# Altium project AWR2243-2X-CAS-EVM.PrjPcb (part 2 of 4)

## Sheet SOC_IO.schdoc
size A2; Date: Not shown in title block; ApprovedBy: Not shown in title block; CheckedBy: Not shown in title block; Author: Not shown in title block; CompanyName: Not shown in title block; DrawnBy: B. Shaffer; Engineer: Not shown in title block; Organization: Not shown in title block; Address1: Not shown in title block; Address2: Not shown in title block; Address3: Not shown in title block; Address4: Not shown in title block; DocumentNumber: 4; Revision: Use project parameter SCH_Rev; SheetNumber: 4; SheetTotal: 17; PageSetup: Record=PageOptions¦CenterHorizontal=True¦CenterVertical=True¦PrintScale=1.00¦XCorrection=1.00¦YCorrection=1.00¦PrintKind=0¦BorderSize=5000000¦LeftOffset=0¦BottomOffset=0¦Orientation=2¦PaperLength=1000¦PaperWidth=1000¦Scale=100¦PaperSource=15¦PrintQuality=600¦MediaType=1¦DitherType=10¦PaperKind=Letter¦PrintScaleMode=1
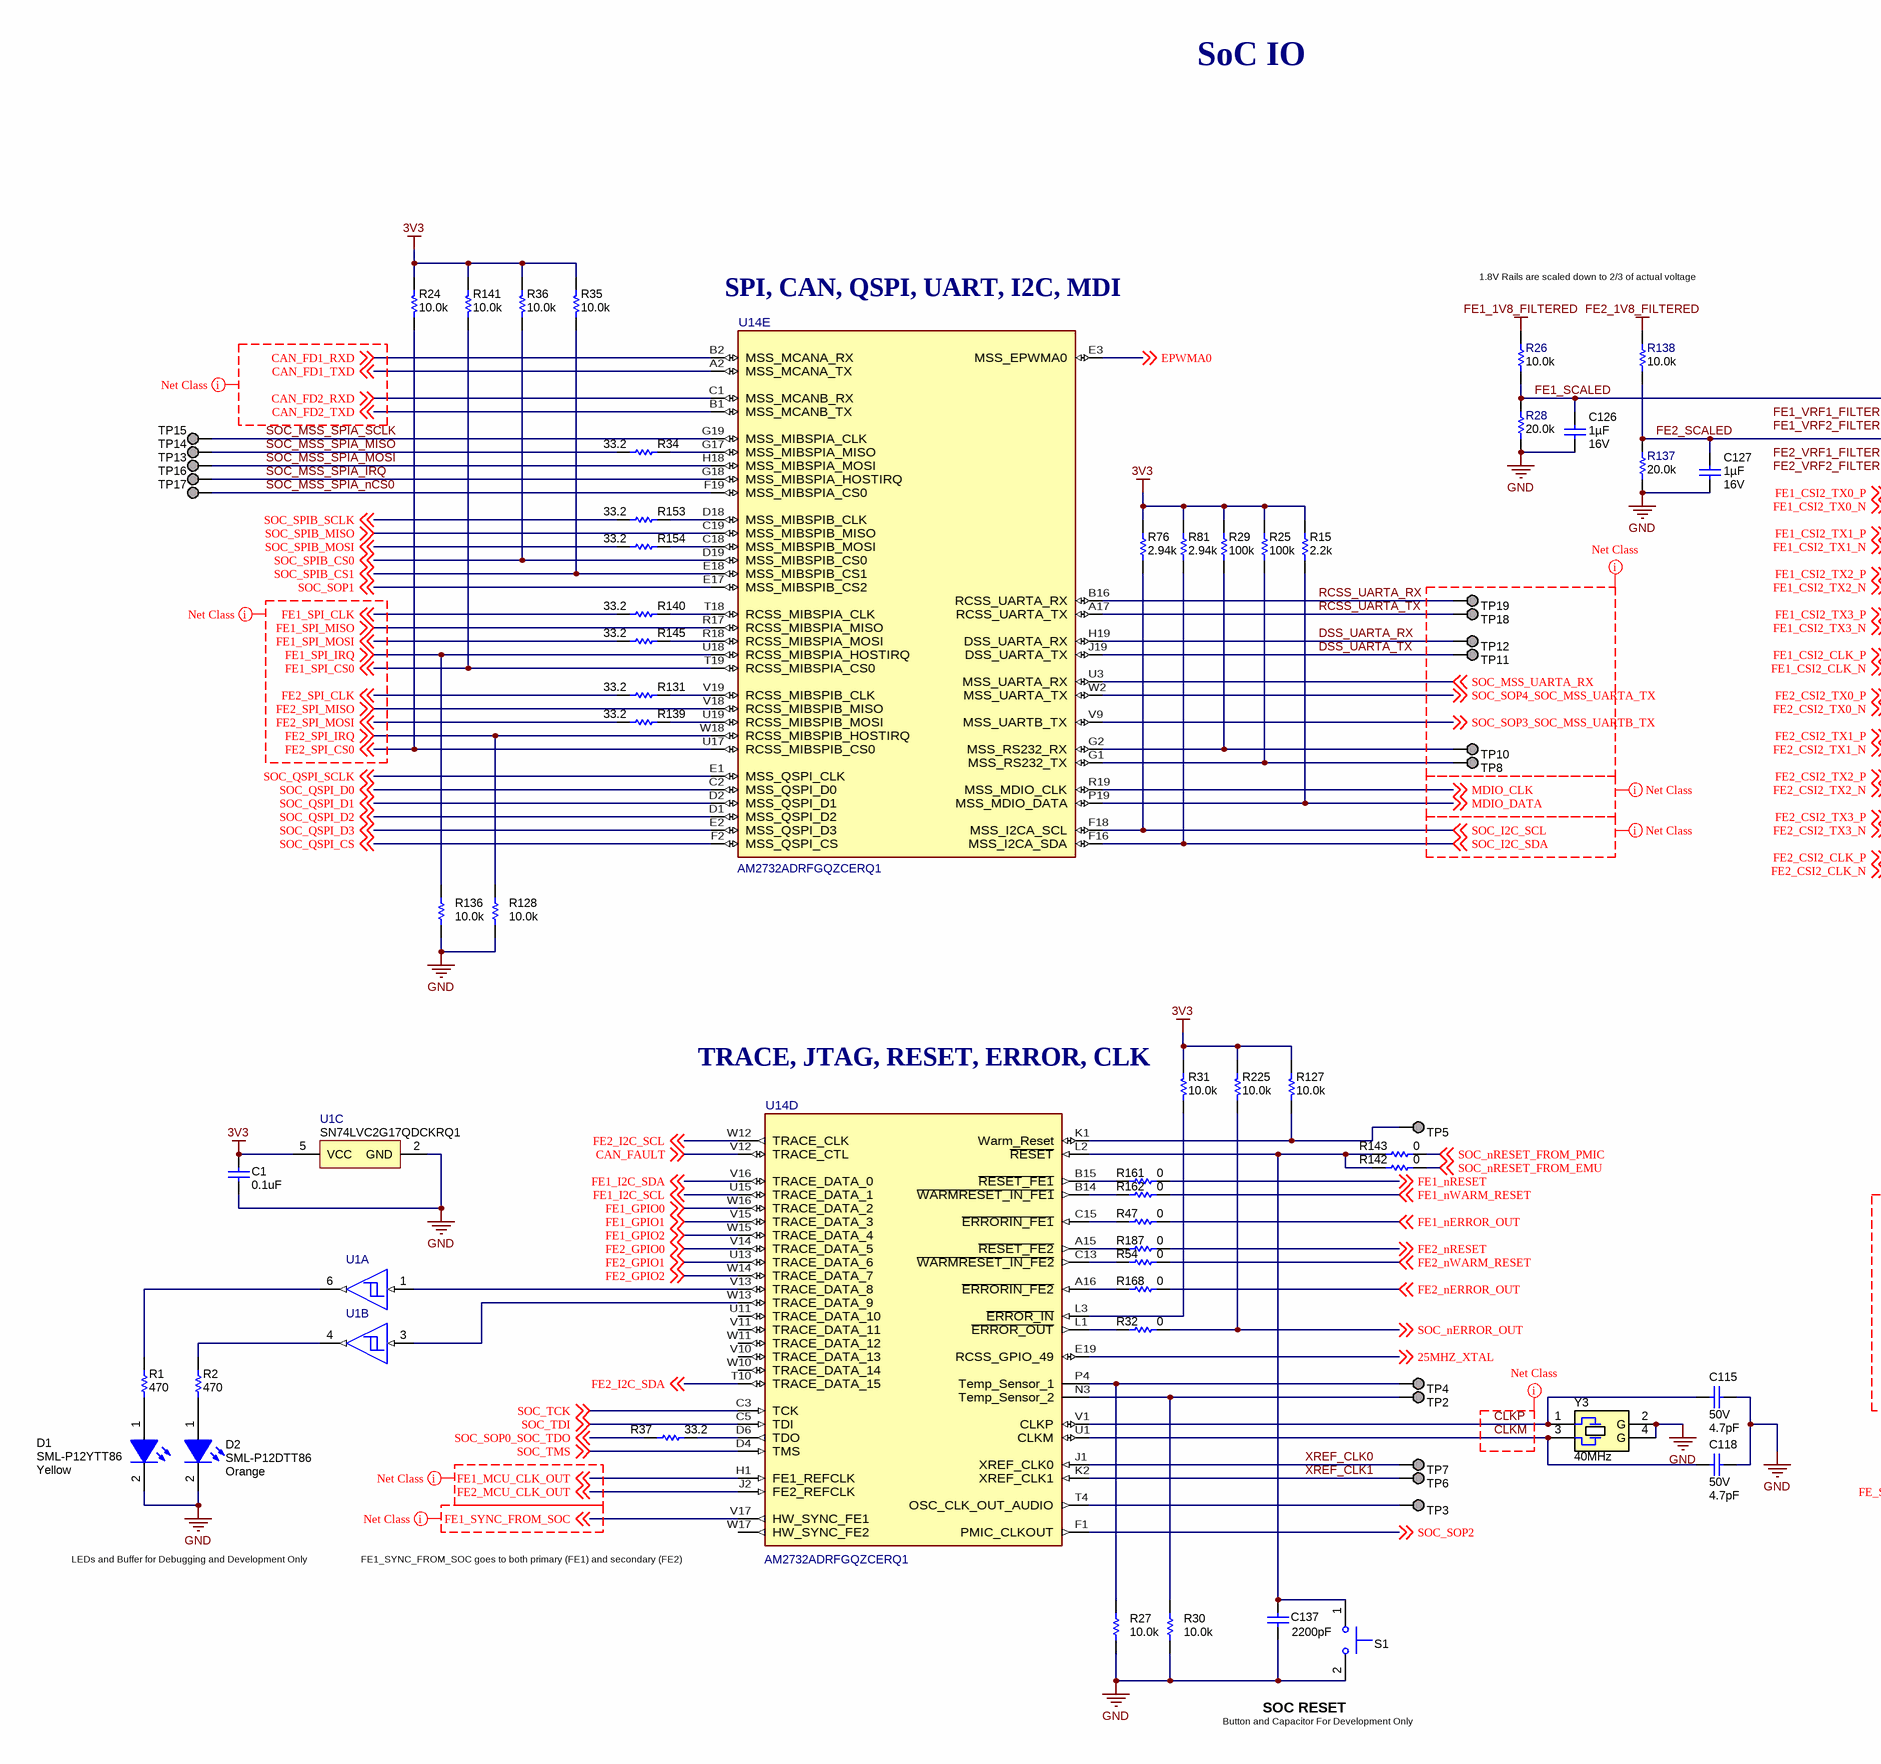
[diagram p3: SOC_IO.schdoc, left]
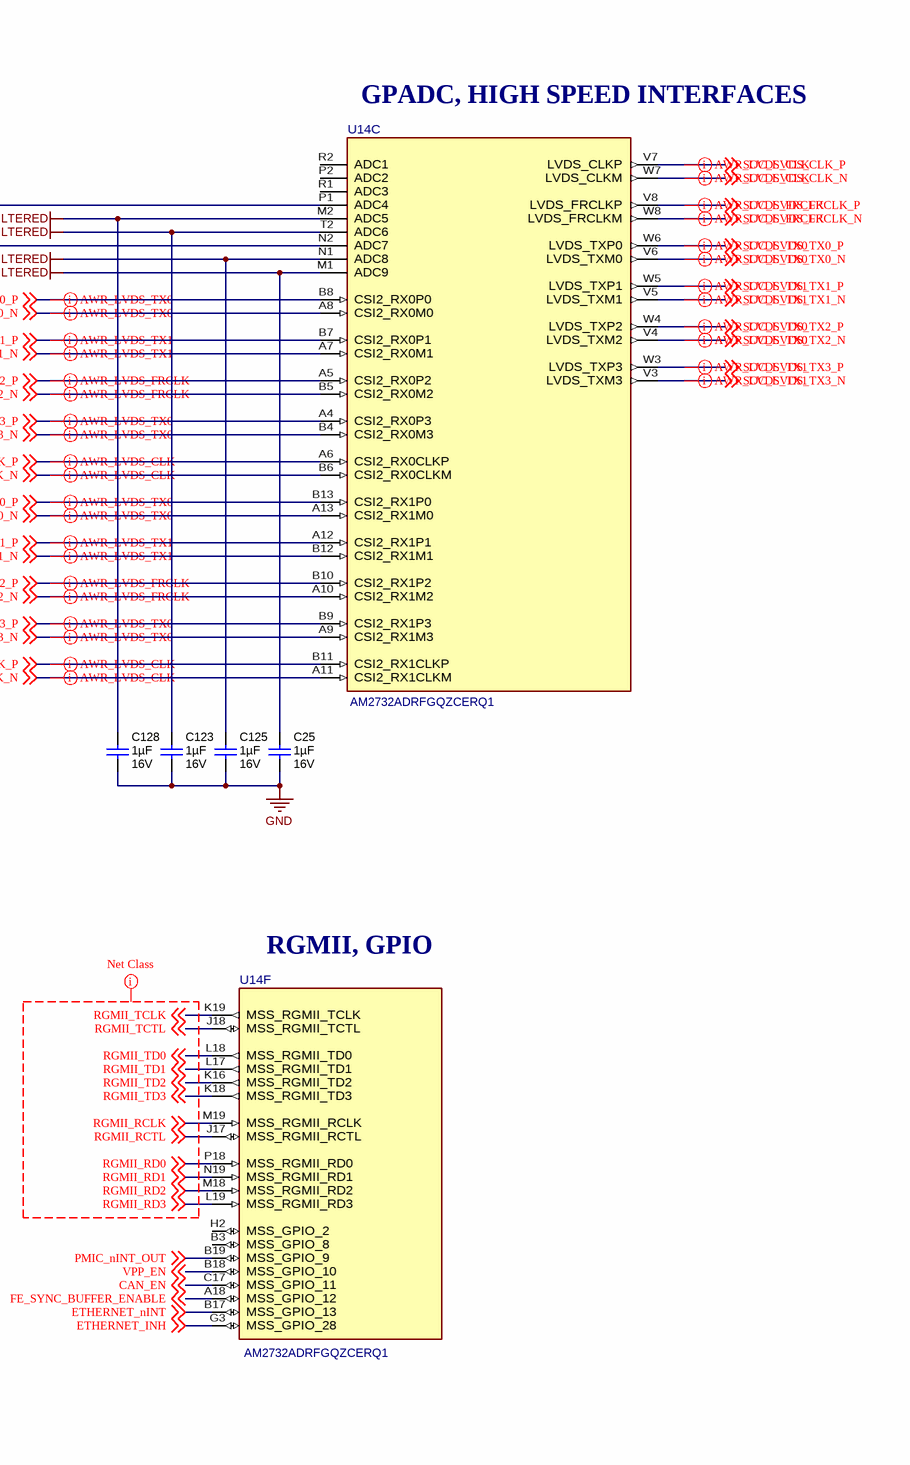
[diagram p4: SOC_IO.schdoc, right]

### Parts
(Parts that share a designator on the sheet are numbered #1, #2 ... from top to bottom, then left to right.)
C1  ValueDisplayed: 0.1uF  [0402L]  (hidden comment: GCM155R71C104KA55D)
C25  VDC_V: 16V  ValueDisplayed: 1µF  [0603S]  (hidden comment: GCM188R71C105KA64J)
C115  VDC_V: 50V  ValueDisplayed: 4.7pF  [0402]  (hidden comment: GJM1555C1H4R7BB01D)
C118  VDC_V: 50V  ValueDisplayed: 4.7pF  [0402]  (hidden comment: GJM1555C1H4R7BB01D)
C123  VDC_V: 16V  ValueDisplayed: 1µF  [0603S]  (hidden comment: GCM188R71C105KA64J)
C125  VDC_V: 16V  ValueDisplayed: 1µF  [0603S]  (hidden comment: GCM188R71C105KA64J)
C126  VDC_V: 16V  ValueDisplayed: 1µF  [0603S]  (hidden comment: GCM188R71C105KA64J)
C127  VDC_V: 16V  ValueDisplayed: 1µF  [0603S]  (hidden comment: GCM188R71C105KA64J)
C128  VDC_V: 16V  ValueDisplayed: 1µF  [0603S]  (hidden comment: GCM188R71C105KA64J)
C137  value 2200pF  [0402]  (hidden comment: UMK105B7222KV-F)
D1  SML-P12YTT86  value Yellow  [LED_SMLP12_YELLOW]
D2  SML-P12DTT86  value Orange  [LED_SMLP12_ORANGE]
R1  ValueDisplayed: 470  [0402]  (hidden comment: ERJ-2RKF4700X)
R2  ValueDisplayed: 470  [0402]  (hidden comment: ERJ-2RKF4700X)
R15  ValueDisplayed: 2.2k  [0402]  (hidden comment: CRCW04022K20JNED)
R24  ValueDisplayed: 10.0k  [0402]  (hidden comment: CRCW040210K0FKED)
R25  ValueDisplayed: 100k  [0402]  (hidden comment: CRCW0402100KFKED)
R26  ValueDisplayed: 10.0k  [0402]  (hidden comment: CRCW040210K0DHEDP)
R27  ValueDisplayed: 10.0k  [0402]  (hidden comment: CRCW040210K0FKED)
R28  ValueDisplayed: 20.0k  [0402]  (hidden comment: CRCW040220K0FKED)
R29  ValueDisplayed: 100k  [0402]  (hidden comment: CRCW0402100KFKED)
R30  ValueDisplayed: 10.0k  [0402]  (hidden comment: CRCW040210K0FKED)
R31  ValueDisplayed: 10.0k  [0402]  (hidden comment: CRCW040210K0FKED)
R32  ValueDisplayed: 0  [0201]  (hidden comment: CRCW02010000Z0ED)
R34  ValueDisplayed: 33.2  [0402]  (hidden comment: CRCW040233R2FKED)
R35  ValueDisplayed: 10.0k  [0402]  (hidden comment: CRCW040210K0FKED)
R36  ValueDisplayed: 10.0k  [0402]  (hidden comment: CRCW040210K0FKED)
R37  ValueDisplayed: 33.2  [0402]  (hidden comment: CRCW040233R2FKED)
R47  ValueDisplayed: 0  [0201]  (hidden comment: CRCW02010000Z0ED)
R54  ValueDisplayed: 0  [0201]  (hidden comment: CRCW02010000Z0ED)
R76  ValueDisplayed: 2.94k  [0402]  (hidden comment: CRCW04022K94FKED)
R81  ValueDisplayed: 2.94k  [0402]  (hidden comment: CRCW04022K94FKED)
R127  ValueDisplayed: 10.0k  [0402]  (hidden comment: CRCW040210K0FKED)
R128  ValueDisplayed: 10.0k  [0402]  (hidden comment: CRCW040210K0FKED)
R131  ValueDisplayed: 33.2  [0402]  (hidden comment: CRCW040233R2FKED)
R136  ValueDisplayed: 10.0k  [0402]  (hidden comment: CRCW040210K0FKED)
R137  ValueDisplayed: 20.0k  [0402]  (hidden comment: CRCW040220K0FKED)
R138  ValueDisplayed: 10.0k  [0402]  (hidden comment: CRCW040210K0DHEDP)
R139  ValueDisplayed: 33.2  [0402]  (hidden comment: CRCW040233R2FKED)
R140  ValueDisplayed: 33.2  [0402]  (hidden comment: CRCW040233R2FKED)
R141  ValueDisplayed: 10.0k  [0402]  (hidden comment: CRCW040210K0FKED)
R142  ValueDisplayed: 0  [0402]  (hidden comment: CRCW04020000Z0ED)
R143  ValueDisplayed: 0  [0402]  (hidden comment: CRCW04020000Z0ED)
R145  ValueDisplayed: 33.2  [0402]  (hidden comment: CRCW040233R2FKED)
R153  ValueDisplayed: 33.2  [0402]  (hidden comment: CRCW040233R2FKED)
R154  ValueDisplayed: 33.2  [0402]  (hidden comment: CRCW040233R2FKED)
R161  ValueDisplayed: 0  [0201]  (hidden comment: CRCW02010000Z0ED)
R162  ValueDisplayed: 0  [0201]  (hidden comment: CRCW02010000Z0ED)
R168  ValueDisplayed: 0  [0201]  (hidden comment: CRCW02010000Z0ED)
R187  ValueDisplayed: 0  [0201]  (hidden comment: CRCW02010000Z0ED)
R225  ValueDisplayed: 10.0k  [0402]  (hidden comment: CRCW040210K0FKED)
S1  SKRKAEE010  [SW_SKRKAEE010]  (value not drawn)
TP2  TP_H0.45P0.75  [TP_H045P075]  (value not drawn)  (no BOM)
TP3  TP_H0.45P0.75  [TP_H045P075]  (value not drawn)  (no BOM)
TP4  TP_H0.45P0.75  [TP_H045P075]  (value not drawn)  (no BOM)
TP5  TP_H0.45P0.75  [TP_H045P075]  (value not drawn)  (no BOM)
TP6  TP_H0.45P0.75  [TP_H045P075]  (value not drawn)  (no BOM)
TP7  TP_H0.45P0.75  [TP_H045P075]  (value not drawn)  (no BOM)
TP8  TP_H0.45P0.75  [TP_H045P075]  (value not drawn)  (no BOM)
TP10  TP_H0.45P0.75  [TP_H045P075]  (value not drawn)  (no BOM)
TP11  TP_H0.45P0.75  [TP_H045P075]  (value not drawn)  (no BOM)
TP12  TP_H0.45P0.75  [TP_H045P075]  (value not drawn)  (no BOM)
TP13  TP_H0.45P0.75  [TP_H045P075]  (value not drawn)  (no BOM)
TP14  TP_H0.45P0.75  [TP_H045P075]  (value not drawn)  (no BOM)
TP15  TP_H0.45P0.75  [TP_H045P075]  (value not drawn)  (no BOM)
TP16  TP_H0.45P0.75  [TP_H045P075]  (value not drawn)  (no BOM)
TP17  TP_H0.45P0.75  [TP_H045P075]  (value not drawn)  (no BOM)
TP18  TP_H0.45P0.75  [TP_H045P075]  (value not drawn)  (no BOM)
TP19  TP_H0.45P0.75  [TP_H045P075]  (value not drawn)  (no BOM)
U1#1  SN74LVC2G17QDCKRQ1  [DCK0006A_N]  (part C of 3)
U1#2  SN74LVC2G17QDCKRQ1  [DCK0006A_N]  (value not drawn)  (parts A,B of 3)
U14#2  AM2732ADRFGQZCERQ1  [ZCE0285A-MFG]  (parts C,D,E,F of 7)
Y3  Frequency_Fixed: 40MHz  [Kyocera_CX3225SA]  (hidden comment: CX3225SA40000D0PTWCC)

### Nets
3V3: C1.2 R15.2 R24.2 R25.2 R29.2 R31.2 R35.2 R36.2 R76.2 R81.2 R127.2 R141.2 R225.2 U1#1.5(VCC)
FE1_1V8_FILTERED: R26.2
FE1_VRF1_FILTERED: C128.1 U14#2.M2(ADC5)
FE1_VRF2_FILTERED: C123.1 U14#2.T2(ADC6)
FE2_1V8_FILTERED: R138.2
FE2_VRF1_FILTERED: C125.1 U14#2.N1(ADC8)
FE2_VRF2_FILTERED: C25.1 U14#2.M1(ADC9)
GND: C1.1 C25.2 C115.2 C118.2 C123.2 C125.2 C126.2 C127.2 C128.2 C137.2 D1.2(K) D2.2(K) R27.1 R28.1 R30.1 R128.1 R136.1 R137.1 S1.2 U1#1.2(GND) Y3.2(GND) Y3.4(GND)
25MHZ_XTAL: U14#2.E19(RCSS_GPIO_49) ; off-sheet 25MHZ_XTAL
CAN_EN: U14#2.C17(MSS_GPIO_11) ; off-sheet CAN_EN
CAN_FAULT: U14#2.V12(TRACE_CTL) ; off-sheet CAN_FAULT
CAN_FD1_RXD: U14#2.B2(MSS_MCANA_RX) ; off-sheet CAN_FD1_RXD
CAN_FD1_TXD: U14#2.A2(MSS_MCANA_TX) ; off-sheet CAN_FD1_TXD
CAN_FD2_RXD: U14#2.C1(MSS_MCANB_RX) ; off-sheet CAN_FD2_RXD
CAN_FD2_TXD: U14#2.B1(MSS_MCANB_TX) ; off-sheet CAN_FD2_TXD
CLKM: C118.1 U14#2.U1(CLKM) Y3.3
CLKP: C115.1 U14#2.V1(CLKP) Y3.1
DSS_UARTA_RX: TP12.1 U14#2.H19(DSS_UARTA_RX)
DSS_UARTA_TX: TP11.1 U14#2.J19(DSS_UARTA_TX)
EPWMA0: U14#2.E3(MSS_EPWMA0) ; off-sheet EPWMA0
ETHERNET_INH: U14#2.G3(MSS_GPIO_28) ; off-sheet ETHERNET_INH
ETHERNET_nINT: U14#2.B17(MSS_GPIO_13) ; off-sheet ETHERNET_nINT
FE1_CSI2_CLK_N: U14#2.B6(CSI2_RX0CLKM) ; off-sheet FE1_CSI2_CLK_N
FE1_CSI2_CLK_P: U14#2.A6(CSI2_RX0CLKP) ; off-sheet FE1_CSI2_CLK_P
FE1_CSI2_TX0_N: U14#2.A8(CSI2_RX0M0) ; off-sheet FE1_CSI2_TX0_N
FE1_CSI2_TX0_P: U14#2.B8(CSI2_RX0P0) ; off-sheet FE1_CSI2_TX0_P
FE1_CSI2_TX1_N: U14#2.A7(CSI2_RX0M1) ; off-sheet FE1_CSI2_TX1_N
FE1_CSI2_TX1_P: U14#2.B7(CSI2_RX0P1) ; off-sheet FE1_CSI2_TX1_P
FE1_CSI2_TX2_N: U14#2.B5(CSI2_RX0M2) ; off-sheet FE1_CSI2_TX2_N
FE1_CSI2_TX2_P: U14#2.A5(CSI2_RX0P2) ; off-sheet FE1_CSI2_TX2_P
FE1_CSI2_TX3_N: U14#2.B4(CSI2_RX0M3) ; off-sheet FE1_CSI2_TX3_N
FE1_CSI2_TX3_P: U14#2.A4(CSI2_RX0P3) ; off-sheet FE1_CSI2_TX3_P
FE1_GPIO0: U14#2.W16(TRACE_DATA_2) ; off-sheet FE1_GPIO0
FE1_GPIO1: U14#2.V15(TRACE_DATA_3) ; off-sheet FE1_GPIO1
FE1_GPIO2: U14#2.W15(TRACE_DATA_4) ; off-sheet FE1_GPIO2
FE1_I2C_SCL: U14#2.U15(TRACE_DATA_1) ; off-sheet FE1_I2C_SCL
FE1_I2C_SDA: U14#2.V16(TRACE_DATA_0) ; off-sheet FE1_I2C_SDA
FE1_MCU_CLK_OUT: U14#2.H1(FE1_REFCLK) ; off-sheet FE1_MCU_CLK_OUT
FE1_nERROR_OUT: R47.2 ; off-sheet FE1_nERROR_OUT
FE1_nRESET: R161.2 ; off-sheet FE1_nRESET
FE1_nWARM_RESET: R162.2 ; off-sheet FE1_nWARM_RESET
FE1_SCALED: C126.1 R26.1 R28.2 U14#2.P1(ADC4)
FE1_SPI_CLK: R140.1 ; off-sheet FE1_SPI_CLK
FE1_SPI_CS0: R141.1 U14#2.T19(RCSS_MIBSPIA_CS0) ; off-sheet FE1_SPI_CS0
FE1_SPI_IRQ: R136.2 U14#2.U18(RCSS_MIBSPIA_HOSTIRQ) ; off-sheet FE1_SPI_IRQ
FE1_SPI_MISO: U14#2.R17(RCSS_MIBSPIA_MISO) ; off-sheet FE1_SPI_MISO
FE1_SPI_MOSI: R145.1 ; off-sheet FE1_SPI_MOSI
FE1_SYNC_FROM_SOC: U14#2.V17(HW_SYNC_FE1) ; off-sheet FE1_SYNC_FROM_SOC
FE2_CSI2_CLK_N: U14#2.A11(CSI2_RX1CLKM) ; off-sheet FE2_CSI2_CLK_N
FE2_CSI2_CLK_P: U14#2.B11(CSI2_RX1CLKP) ; off-sheet FE2_CSI2_CLK_P
FE2_CSI2_TX0_N: U14#2.A13(CSI2_RX1M0) ; off-sheet FE2_CSI2_TX0_N
FE2_CSI2_TX0_P: U14#2.B13(CSI2_RX1P0) ; off-sheet FE2_CSI2_TX0_P
FE2_CSI2_TX1_N: U14#2.B12(CSI2_RX1M1) ; off-sheet FE2_CSI2_TX1_N
FE2_CSI2_TX1_P: U14#2.A12(CSI2_RX1P1) ; off-sheet FE2_CSI2_TX1_P
FE2_CSI2_TX2_N: U14#2.A10(CSI2_RX1M2) ; off-sheet FE2_CSI2_TX2_N
FE2_CSI2_TX2_P: U14#2.B10(CSI2_RX1P2) ; off-sheet FE2_CSI2_TX2_P
FE2_CSI2_TX3_N: U14#2.A9(CSI2_RX1M3) ; off-sheet FE2_CSI2_TX3_N
FE2_CSI2_TX3_P: U14#2.B9(CSI2_RX1P3) ; off-sheet FE2_CSI2_TX3_P
FE2_GPIO0: U14#2.V14(TRACE_DATA_5) ; off-sheet FE2_GPIO0
FE2_GPIO1: U14#2.U13(TRACE_DATA_6) ; off-sheet FE2_GPIO1
FE2_GPIO2: U14#2.W14(TRACE_DATA_7) ; off-sheet FE2_GPIO2
FE2_I2C_SCL: U14#2.W12(TRACE_CLK) ; off-sheet FE2_I2C_SCL
FE2_I2C_SDA: U14#2.T10(TRACE_DATA_15) ; off-sheet FE2_I2C_SDA
FE2_MCU_CLK_OUT: U14#2.J2(FE2_REFCLK) ; off-sheet FE2_MCU_CLK_OUT
FE2_nERROR_OUT: R168.2 ; off-sheet FE2_nERROR_OUT
FE2_nRESET: R187.2 ; off-sheet FE2_nRESET
FE2_nWARM_RESET: R54.2 ; off-sheet FE2_nWARM_RESET
FE2_SCALED: C127.1 R137.2 R138.1 U14#2.N2(ADC7)
FE2_SPI_CLK: R131.1 ; off-sheet FE2_SPI_CLK
FE2_SPI_CS0: R24.1 U14#2.U17(RCSS_MIBSPIB_CS0) ; off-sheet FE2_SPI_CS0
FE2_SPI_IRQ: R128.2 U14#2.W18(RCSS_MIBSPIB_HOSTIRQ) ; off-sheet FE2_SPI_IRQ
FE2_SPI_MISO: U14#2.V18(RCSS_MIBSPIB_MISO) ; off-sheet FE2_SPI_MISO
FE2_SPI_MOSI: R139.1 ; off-sheet FE2_SPI_MOSI
FE_SYNC_BUFFER_ENABLE: U14#2.A18(MSS_GPIO_12) ; off-sheet FE_SYNC_BUFFER_ENABLE
MDIO_CLK: U14#2.R19(MSS_MDIO_CLK) ; off-sheet MDIO_CLK
MDIO_DATA: R15.1 U14#2.P19(MSS_MDIO_DATA) ; off-sheet MDIO_DATA
PMIC_nINT_OUT: U14#2.B19(MSS_GPIO_9) ; off-sheet PMIC_nINT_OUT
RCSS_UARTA_RX: TP19.1 U14#2.B16(RCSS_UARTA_RX)
RCSS_UARTA_TX: TP18.1 U14#2.A17(RCSS_UARTA_TX)
RGMII_RCLK: U14#2.M19(MSS_RGMII_RCLK) ; off-sheet RGMII_RCLK
RGMII_RCTL: U14#2.J17(MSS_RGMII_RCTL) ; off-sheet RGMII_RCTL
RGMII_RD0: U14#2.P18(MSS_RGMII_RD0) ; off-sheet RGMII_RD0
RGMII_RD1: U14#2.N19(MSS_RGMII_RD1) ; off-sheet RGMII_RD1
RGMII_RD2: U14#2.M18(MSS_RGMII_RD2) ; off-sheet RGMII_RD2
RGMII_RD3: U14#2.L19(MSS_RGMII_RD3) ; off-sheet RGMII_RD3
RGMII_TCLK: U14#2.K19(MSS_RGMII_TCLK) ; off-sheet RGMII_TCLK
RGMII_TCTL: U14#2.J18(MSS_RGMII_TCTL) ; off-sheet RGMII_TCTL
RGMII_TD0: U14#2.L18(MSS_RGMII_TD0) ; off-sheet RGMII_TD0
RGMII_TD1: U14#2.L17(MSS_RGMII_TD1) ; off-sheet RGMII_TD1
RGMII_TD2: U14#2.K16(MSS_RGMII_TD2) ; off-sheet RGMII_TD2
RGMII_TD3: U14#2.K18(MSS_RGMII_TD3) ; off-sheet RGMII_TD3
SOC_I2C_SCL: R76.1 U14#2.F18(MSS_I2CA_SCL) ; off-sheet SOC_I2C_SCL
SOC_I2C_SDA: R81.1 U14#2.F16(MSS_I2CA_SDA) ; off-sheet SOC_I2C_SDA
SOC_LVDS_CLK_N: U14#2.W7(LVDS_CLKM) ; off-sheet SOC_LVDS_CLK_N
SOC_LVDS_CLK_P: U14#2.V7(LVDS_CLKP) ; off-sheet SOC_LVDS_CLK_P
SOC_LVDS_FRCLK_N: U14#2.W8(LVDS_FRCLKM) ; off-sheet SOC_LVDS_FRCLK_N
SOC_LVDS_FRCLK_P: U14#2.V8(LVDS_FRCLKP) ; off-sheet SOC_LVDS_FRCLK_P
SOC_LVDS_TX0_N: U14#2.V6(LVDS_TXM0) ; off-sheet SOC_LVDS_TX0_N
SOC_LVDS_TX0_P: U14#2.W6(LVDS_TXP0) ; off-sheet SOC_LVDS_TX0_P
SOC_LVDS_TX1_N: U14#2.V5(LVDS_TXM1) ; off-sheet SOC_LVDS_TX1_N
SOC_LVDS_TX1_P: U14#2.W5(LVDS_TXP1) ; off-sheet SOC_LVDS_TX1_P
SOC_LVDS_TX2_N: U14#2.V4(LVDS_TXM2) ; off-sheet SOC_LVDS_TX2_N
SOC_LVDS_TX2_P: U14#2.W4(LVDS_TXP2) ; off-sheet SOC_LVDS_TX2_P
SOC_LVDS_TX3_N: U14#2.V3(LVDS_TXM3) ; off-sheet SOC_LVDS_TX3_N
SOC_LVDS_TX3_P: U14#2.W3(LVDS_TXP3) ; off-sheet SOC_LVDS_TX3_P
SOC_MSS_SPIA_IRQ: TP16.1 U14#2.G18(MSS_MIBSPIA_HOSTIRQ)
SOC_MSS_SPIA_MISO: R34.1 TP14.1
SOC_MSS_SPIA_MOSI: TP13.1 U14#2.H18(MSS_MIBSPIA_MOSI)
SOC_MSS_SPIA_nCS0: TP17.1 U14#2.F19(MSS_MIBSPIA_CS0)
SOC_MSS_SPIA_SCLK: TP15.1 U14#2.G19(MSS_MIBSPIA_CLK)
SOC_MSS_UARTA_RX: U14#2.U3(MSS_UARTA_RX) ; off-sheet SOC_MSS_UARTA_RX
SOC_nERROR_OUT: R32.2 R225.1 ; off-sheet SOC_nERROR_OUT
SOC_nRESET_FROM_EMU: R142.1 ; off-sheet SOC_nRESET_FROM_EMU
SOC_nRESET_FROM_PMIC: R143.1 ; off-sheet SOC_nRESET_FROM_PMIC
SOC_QSPI_CS: U14#2.F2(MSS_QSPI_CS) ; off-sheet SOC_QSPI_CS
SOC_QSPI_D0: U14#2.C2(MSS_QSPI_D0) ; off-sheet SOC_QSPI_D0
SOC_QSPI_D1: U14#2.D2(MSS_QSPI_D1) ; off-sheet SOC_QSPI_D1
SOC_QSPI_D2: U14#2.D1(MSS_QSPI_D2) ; off-sheet SOC_QSPI_D2
SOC_QSPI_D3: U14#2.E2(MSS_QSPI_D3) ; off-sheet SOC_QSPI_D3
SOC_QSPI_SCLK: U14#2.E1(MSS_QSPI_CLK) ; off-sheet SOC_QSPI_SCLK
SOC_SOP0_SOC_TDO: R37.1 ; off-sheet SOC_SOP0_SOC_TDO
SOC_SOP1: U14#2.E17(MSS_MIBSPIB_CS2) ; off-sheet SOC_SOP1
SOC_SOP2: U14#2.F1(PMIC_CLKOUT) ; off-sheet SOC_SOP2
SOC_SOP3_SOC_MSS_UARTB_TX: U14#2.V9(MSS_UARTB_TX) ; off-sheet SOC_SOP3_SOC_MSS_UARTB_TX
SOC_SOP4_SOC_MSS_UARTA_TX: U14#2.W2(MSS_UARTA_TX) ; off-sheet SOC_SOP4_SOC_MSS_UARTA_TX
SOC_SPIB_CS0: R36.1 U14#2.D19(MSS_MIBSPIB_CS0) ; off-sheet SOC_SPIB_CS0
SOC_SPIB_CS1: R35.1 U14#2.E18(MSS_MIBSPIB_CS1) ; off-sheet SOC_SPIB_CS1
SOC_SPIB_MISO: U14#2.C19(MSS_MIBSPIB_MISO) ; off-sheet SOC_SPIB_MISO
SOC_SPIB_MOSI: R154.1 ; off-sheet SOC_SPIB_MOSI
SOC_SPIB_SCLK: R153.1 ; off-sheet SOC_SPIB_SCLK
SOC_TCK: U14#2.C3(TCK) ; off-sheet SOC_TCK
SOC_TDI: U14#2.C5(TDI) ; off-sheet SOC_TDI
SOC_TMS: U14#2.D4(TMS) ; off-sheet SOC_TMS
VPP_EN: U14#2.B18(MSS_GPIO_10) ; off-sheet VPP_EN
XREF_CLK0: TP7.1 U14#2.J1(XREF_CLK0)
XREF_CLK1: TP6.1 U14#2.K2(XREF_CLK1)
NetC137_1: C137.1 R142.2 R143.2 S1.1 U14#2.L2(~{RESET})
NetD1_1: D1.1(A) R1.1
NetD2_1: D2.1(A) R2.1
NetR1_2: R1.2 U1#2.6(1Y)
NetR2_2: R2.2 U1#2.4(2Y)
NetR25_1: R25.1 TP8.1 U14#2.G1(MSS_RS232_TX)
NetR27_2: R27.2 TP4.1 U14#2.P4(Temp_Sensor_1)
NetR29_1: R29.1 TP10.1 U14#2.G2(MSS_RS232_RX)
NetR30_2: R30.2 TP2.1 U14#2.N3(Temp_Sensor_2)
NetR31_1: R31.1 U14#2.L3(~{ERROR_IN})
NetR32_1: R32.1 U14#2.L1(~{ERROR_OUT})
NetR34_2: R34.2 U14#2.G17(MSS_MIBSPIA_MISO)
NetR37_2: R37.2 U14#2.D6(TDO)
NetR47_1: R47.1 U14#2.C15(~{ERRORIN_FE1})
NetR54_1: R54.1 U14#2.C13(~{WARMRESET_IN_FE2})
NetR127_1: R127.1 TP5.1 U14#2.K1(Warm_Reset)
NetR131_2: R131.2 U14#2.V19(RCSS_MIBSPIB_CLK)
NetR139_2: R139.2 U14#2.U19(RCSS_MIBSPIB_MOSI)
NetR140_2: R140.2 U14#2.T18(RCSS_MIBSPIA_CLK)
NetR145_2: R145.2 U14#2.R18(RCSS_MIBSPIA_MOSI)
NetR153_2: R153.2 U14#2.D18(MSS_MIBSPIB_CLK)
NetR154_2: R154.2 U14#2.C18(MSS_MIBSPIB_MOSI)
NetR161_1: R161.1 U14#2.B15(~{RESET_FE1})
NetR162_1: R162.1 U14#2.B14(~{WARMRESET_IN_FE1})
NetR168_1: R168.1 U14#2.A16(~{ERRORIN_FE2})
NetR187_1: R187.1 U14#2.A15(~{RESET_FE2})
NetTP3_1: TP3.1 U14#2.T4(OSC_CLK_OUT_AUDIO)
NetU1#2_1: U1#2.1(1A) U14#2.V13(TRACE_DATA_8)
NetU1#2_3: U1#2.3(2A) U14#2.W13(TRACE_DATA_9)

Not connected (* = marked no-connect by the designer): U14#2 B3(MSS_GPIO_8) H2(MSS_GPIO_2) P2(ADC2) R1(ADC3) R2(ADC1) U11(TRACE_DATA_10) V10(TRACE_DATA_13) V11(TRACE_DATA_11) W10(TRACE_DATA_14) W11(TRACE_DATA_12) W17(HW_SYNC_FE2)

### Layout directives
net class FE_SPI: FE1_SPI_CLK, FE1_SPI_CS0, FE1_SPI_IRQ, FE1_SPI_MISO, FE1_SPI_MOSI, FE2_SPI_CLK, FE2_SPI_CS0, FE2_SPI_IRQ, FE2_SPI_MISO, FE2_SPI_MOSI
net class CAN: CAN_FD1_RXD, CAN_FD1_TXD, CAN_FD2_RXD, CAN_FD2_TXD
net class SOC_40MHz_CLK: CLKM, CLKP
net class RGMII: RGMII_RCLK, RGMII_RCTL, RGMII_RD0, RGMII_RD1, RGMII_RD2, RGMII_RD3, RGMII_TCLK, RGMII_TCTL, RGMII_TD0, RGMII_TD1, RGMII_TD2, RGMII_TD3
net class UART: SOC_MSS_UARTA_RX, SOC_SOP3_SOC_MSS_UARTB_TX, SOC_SOP4_SOC_MSS_UARTA_TX
net class FE_REFCLK: FE1_MCU_CLK_OUT, FE2_MCU_CLK_OUT
net class FE_HWSYNC: FE1_SYNC_FROM_SOC
net class MDIO: MDIO_CLK, MDIO_DATA
net class I2C: SOC_I2C_SCL, SOC_I2C_SDA
differential pair: FE1_CSI2_CLK_N, FE1_CSI2_CLK_P, FE1_CSI2_TX0_N, FE1_CSI2_TX0_P, FE1_CSI2_TX1_N, FE1_CSI2_TX1_P, FE1_CSI2_TX2_N, FE1_CSI2_TX2_P, FE1_CSI2_TX3_N, FE1_CSI2_TX3_P, FE2_CSI2_CLK_N, FE2_CSI2_CLK_P, FE2_CSI2_TX0_N, FE2_CSI2_TX0_P, FE2_CSI2_TX1_N, FE2_CSI2_TX1_P, FE2_CSI2_TX2_N, FE2_CSI2_TX2_P, FE2_CSI2_TX3_N, FE2_CSI2_TX3_P, SOC_LVDS_CLK_N, SOC_LVDS_CLK_P, SOC_LVDS_FRCLK_N, SOC_LVDS_FRCLK_P, SOC_LVDS_TX0_N, SOC_LVDS_TX0_P, SOC_LVDS_TX1_N, SOC_LVDS_TX1_P, SOC_LVDS_TX2_N, SOC_LVDS_TX2_P, SOC_LVDS_TX3_N, SOC_LVDS_TX3_P

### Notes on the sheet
- SoC IO
- SPI, CAN, QSPI, UART, I2C, MDI
- 1.8V Rails are scaled down to 2/3 of actual voltage
- GPADC, HIGH SPEED INTERFACES
- TRACE, JTAG, RESET, ERROR, CLK
- RGMII, GPIO
- LEDs and Buffer for Debugging and Development Only
- FE1_SYNC_FROM_SOC goes to both primary (FE1) and secondary (FE2)
- SOC RESET
- Button and Capacitor For Development Only

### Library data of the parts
C1 = CMP-0006351-2: CAP, CERM, 0.1 uF, 16 V, +/- 10%, X7R, 0402; Manufacturer: MuRata; TaMin_C: -55°C; Polarized: N; SizeAreaWB_mm2: 3; Value1: Unknown; U/M: EA; Value: 0.1uF; TaMax_C: 125°C; SizeZ_mm: 0.6; SizeX_mm: 1; SizeY_mm: 0.5; Cap_Case: 0402; Value2: 16V; Cap_F: 100nF; AEC Category: Q200
C25 C123 C125-C128 = CMP-0079154-1: CAP, CERM, 1 µF, 16 V,+/- 10%, X7R, AEC-Q200 Grade 1, 0603; Manufacturer: MuRata; SizeAreaWB_mm2: 4.68; SizeArea_mm2: 1.28; AEC Qualified: Y; AEC Category: Q200; Value: 1uF; TaMax_C: 125°C; SizeZ_mm: 1; Polarized: N; TaMin_C: -55°C; SizeY_mm: 0.8; U/M: EA; SizeX_mm: 1.6; Cap_Case: 0603
C115 C118 = CMP-0006367-2: CAP, CERM, 4.7 pF, 50 V, +/- 2%, C0G/NP0, 0402; Manufacturer: MuRata; TaMin_C: -55°C; Polarized: N; SizeAreaWB_mm2: 3; Value1: Unknown; U/M: EA; Value: 4.7pF; TaMax_C: 125°C; SizeZ_mm: 0.6; SizeX_mm: 1; SizeY_mm: 0.5; AEC Category: Q200
C137 = Capacitor: Cap, Cer-X7R, 2200pF, 50V, 10%, 0402; Manufacturer: Taiyo Yuden; PART Name: SCH_LIB\CAP_NP; Polarized: N; U/M: EA; TempCo: X7R; DECAL Name: 0402,0402_HD; EN: 102-1-00062; Onhand: 7818
D1 = CMP-0002839-2: LED, Yellow, SMD; Manufacturer: Rohm; Vf_V: 2.1V; Tjmax_C: 85°C; Value1: W; Type: InGaN; Io_A: 20mA
D2 = CMP-0002841-1: LED, Orange, SMD; Manufacturer: Rohm; Io_A: 20mA; Tjmax_C: 85°C; Value1: W; U/M: EA; Vf_V: 2.1V; Type: InGaN
R1 R2 = CMP-0026699-1: RES, 470, 1%, 0.1 W, AEC-Q200 Grade 0, 0402; Manufacturer: Panasonic; Power_W: 100mW; TempCo: 100 ppm/C; Value_Code: 470R; U/M: EA; Value: 470; SizeX_mm: 1; SizeY_mm: 0.5; SizeZ_mm: 0.6; Value2: 0.1W; AEC Qualified: Y; VDC_V: 50V; AEC Grade: 0; AEC Category: Q200
R15 = CMP-0026890-5: RES, 2.2 k, 5%, 0.063 W, AEC-Q200 Grade 0, 0402; Manufacturer: Vishay-Dale; Power_W: 63mW; TempCo: 200 ppm/C; Value_Code: 2k20; Value: 2.2k; EIA_Code: E24; SizeX_mm: 1; SizeY_mm: 0.5; SizeZ_mm: 0.6; Value2: 0.063W; AEC Qualified: Y; VDC_V: 50V; AEC Category: Q200; AEC Grade: 0
R24 R27 R30 R31 R35 R36 R127 R128 R136 R141 R225 = CMP-0025958-3: RES, 10.0 k, 1%, 0.063 W, AEC-Q200 Grade 0, 0402; Manufacturer: Vishay-Dale; Power_W: 63mW; TempCo: 100 ppm/C; Value_Code: 10k0; Value: 10.0k; EIA_Code: E96; Res_ohm: 10k; SizeX_mm: 1; SizeY_mm: 0.5; SizeZ_mm: 0.6; Value2: 0.063W; CompType: Resistor; AEC Qualified: Y; VDC_V: 50V; AEC Category: Q200; AEC Grade: 0; INSTALLATION: DNP
R25 R29 = CMP-0025950-3: RES, 100 k, 1%, 0.063 W, AEC-Q200 Grade 0, 0402; Manufacturer: Vishay-Dale; Power_W: 63mW; TempCo: 100 ppm/C; Value: 100k; EIA_Code: E96; SizeX_mm: 1; SizeY_mm: 0.5; SizeZ_mm: 0.6; Value2: 0.063W; AEC Qualified: Y; VDC_V: 50V; AEC Category: Q200; AEC Grade: 0
R26 = CMP-0026769-2: RES, 10.0 k, 0.5%, 0.063 W, AEC-Q200 Grade 0, 0402; Manufacturer: Vishay-Dale; Power_W: 63mW; TempCo: 50 ppm/C; Value_Code: 10k0; Value: 10.0k; EIA_Code: E192; Res_ohm: 10k; SizeX_mm: 1; SizeY_mm: 0.5; SizeZ_mm: 0.6; Value2: 0.063W; CompType: Resistor; AEC Qualified: Y; VDC_V: 50V; AEC Category: Q200; AEC Grade: 0
R28 R137 = CMP-0026162-2: RES, 20.0 k, 1%, 0.063 W, AEC-Q200 Grade 0, 0402; Manufacturer: Vishay-Dale; Power_W: 63mW; TempCo: 100 ppm/C; Value_Code: 20k0; Value: 20.0k; EIA_Code: E96; Res_ohm: 20k; SizeX_mm: 1; SizeY_mm: 0.5; SizeZ_mm: 0.6; Value2: 0.063W; AEC Qualified: Y; VDC_V: 50V; AEC Category: Q200; AEC Grade: 0
R32 R47 R54 R161 R162 R168 R187 = CMP-0027008-4: RES, 0, 5%, 0.05 W, 0201; Manufacturer: Vishay-Dale; Power_W: 50mW; TempCo: ppm/C; Value_Code: 0000; Value: 0; EIA_Code: E24; SizeX_mm: 0.6; SizeY_mm: 0.3; SizeZ_mm: 0.26; Value2: 0.05W; SizeArea_mm2: 0.18; AEC Qualified: N; AEC Category: Q200
R34 R37 R131 R139 R140 R145 R153 R154 = CMP-0026299-2: RES, 33.2, 1%, 0.063 W, AEC-Q200 Grade 0, 0402; Manufacturer: Vishay-Dale; Power_W: 63mW; TempCo: 100 ppm/C; Value_Code: 33R2; Value: 33.2; EIA_Code: E96; SizeX_mm: 1; SizeY_mm: 0.5; SizeZ_mm: 0.6; Value2: 0.063W; AEC Qualified: Y; VDC_V: 50V; AEC Category: Q200; AEC Grade: 0
R76 R81 = CMP-0026244-2: RES, 2.94 k, 1%, 0.063 W, AEC-Q200 Grade 0, 0402; Manufacturer: Vishay-Dale; Power_W: 63mW; TempCo: 100 ppm/C; Value_Code: 2k94; Value: 2.94k; EIA_Code: E96; SizeX_mm: 1; SizeY_mm: 0.5; SizeZ_mm: 0.6; Value2: 0.063W; AEC Qualified: Y; VDC_V: 50V; AEC Category: Q200; AEC Grade: 0
R138 = CMP-0026769-2: RES, 10.0 k, 0.5%, 0.063 W, AEC-Q200 Grade 0, 0402; Manufacturer: Vishay-Dale; Power_W: 63mW; TempCo: 50 ppm/C; Value_Code: 10k0; Value: 10.0k; EIA_Code: E192; Res_ohm: 10k; SizeX_mm: 1; SizeY_mm: 0.5; SizeZ_mm: 0.6; Value2: 0.063W; AEC Qualified: Y; VDC_V: 50V; AEC Category: Q200; AEC Grade: 0
R142 R143 = CMP-0026822-3: RES, 0, 5%, 0.063 W, AEC-Q200 Grade 0, 0402; Manufacturer: Vishay-Dale; Power_W: 63mW; TempCo: 200 ppm/C; Value_Code: 0000; Value: 0; EIA_Code: E24; SizeX_mm: 1; SizeY_mm: 0.5; SizeZ_mm: 0.6; Value2: 0.063W; AEC Qualified: Y; VDC_V: 50V; AEC Category: Q200
S1 = SKRKAEE010: Switch, Tactile, 12v, 50mA, Vertical, SMD; Manufacturer: Alps; Alternate Manufacturer: Any; Alternate PartNumber: Equivalent; SymbolCreator: a0412235; Circuit: SPST-NO; VDC_V: 12; SwitchFunction: Off-Mom; PositionCount: 1; CurrentRating_mA: 50; EN: 205-1-00046; Mfg: ALPS ELECTRIC CO., LTD; Onhand: 0
TP2-TP8 TP10-TP19 = CMP-0003719-1: Testpoint; Manufacturer: Texas Instruments; CompType: Pad
U1#1 U1#2 = CMP-0051906-3: Automotive Catalog Dual Schmitt-Trigger Buffer, DCK0006A (SOT-SC70-6); Manufacturer: Texas Instruments; Generic Part Number: SN74LVC2G17-Q1; Output Type: CMOS; Bits(#): 2; Input Type: CMOS/TTL; Technology Family: LVC; Schmitt Trigger: Yes; 3-State Output: No; VCC(Max)(V): 5.5; Output Drive (IOL/IOH)(Max)(mA): 32/-32; ICC @ Nom Voltage(Max)(mA): 0.01; VCC(Min)(V): 1.65; F @ Nom Voltage(Max)(Mhz): 150; Logic: True; Voltage(Nom)(V): 1.8,2.5,3.3,5; tpd @ Nom Voltage(Max)(ns): 9.3,5.7,5.4,4.3; AEC Category: Q200; AEC Qualified: Y; CompType: IC; SizeAreaWB_mm2: 9.3; SizeArea_mm2: 4.2; SizeX_mm: 2.1; SizeY_mm: 2.0; SizeZ_mm: 1.1
U14#2 = CMP-0088502-3: No description; Manufacturer: Texas Instruments; SizeZ_mm: 1.3mm; Number Of Uart Channels: 2; Standoff Height: 0.23mm; Number Of A/D Converters: 1; CompType: IC; Number Of Pwm Channels: 3; Number Of Adc Channels: 9; AEC Category: Q200; Interface: I2C,SPI,UART,CAN,Ethernet,LVDS,Other
Y3 = CMP-0004694-2: Crystal, 40 MHz, 8pF, SMD; Manufacturer: Kyocera; TaMin_C: -40°C; Frequency Stability: +/-200ppm; SizeAreaWB_mm2: 14.7; U/M: EA; TaMax_C: 125°C; SizeZ_mm: 0.8; SizeX_mm: 2.5; SizeY_mm: 3.2; SizeArea_mm2: 8

## Sheet SOC_FLASH_SOP.SchDoc
size 431 x 279 mm; Date: Not shown in title block; ApprovedBy: Not shown in title block; CheckedBy: Not shown in title block; Author: Not shown in title block; CompanyName: Not shown in title block; DrawnBy: B. Shaffer; Engineer: Not shown in title block; Organization: Not shown in title block; Address1: Not shown in title block; Address2: Not shown in title block; Address3: Not shown in title block; Address4: Not shown in title block; DocumentNumber: 5; Revision: Use project parameter SCH_Rev; SheetNumber: 5; SheetTotal: 17; PageSetup: Record=PageOptions¦CenterHorizontal=True¦CenterVertical=True¦PrintScale=1.00¦XCorrection=1.00¦YCorrection=1.00¦PrintKind=0¦BorderSize=5000000¦LeftOffset=0¦BottomOffset=0¦Orientation=2¦PaperLength=1000¦PaperWidth=1000¦Scale=100¦PaperSource=15¦PrintQuality=600¦MediaType=1¦DitherType=10¦PaperKind=Letter¦PrintScaleMode=1
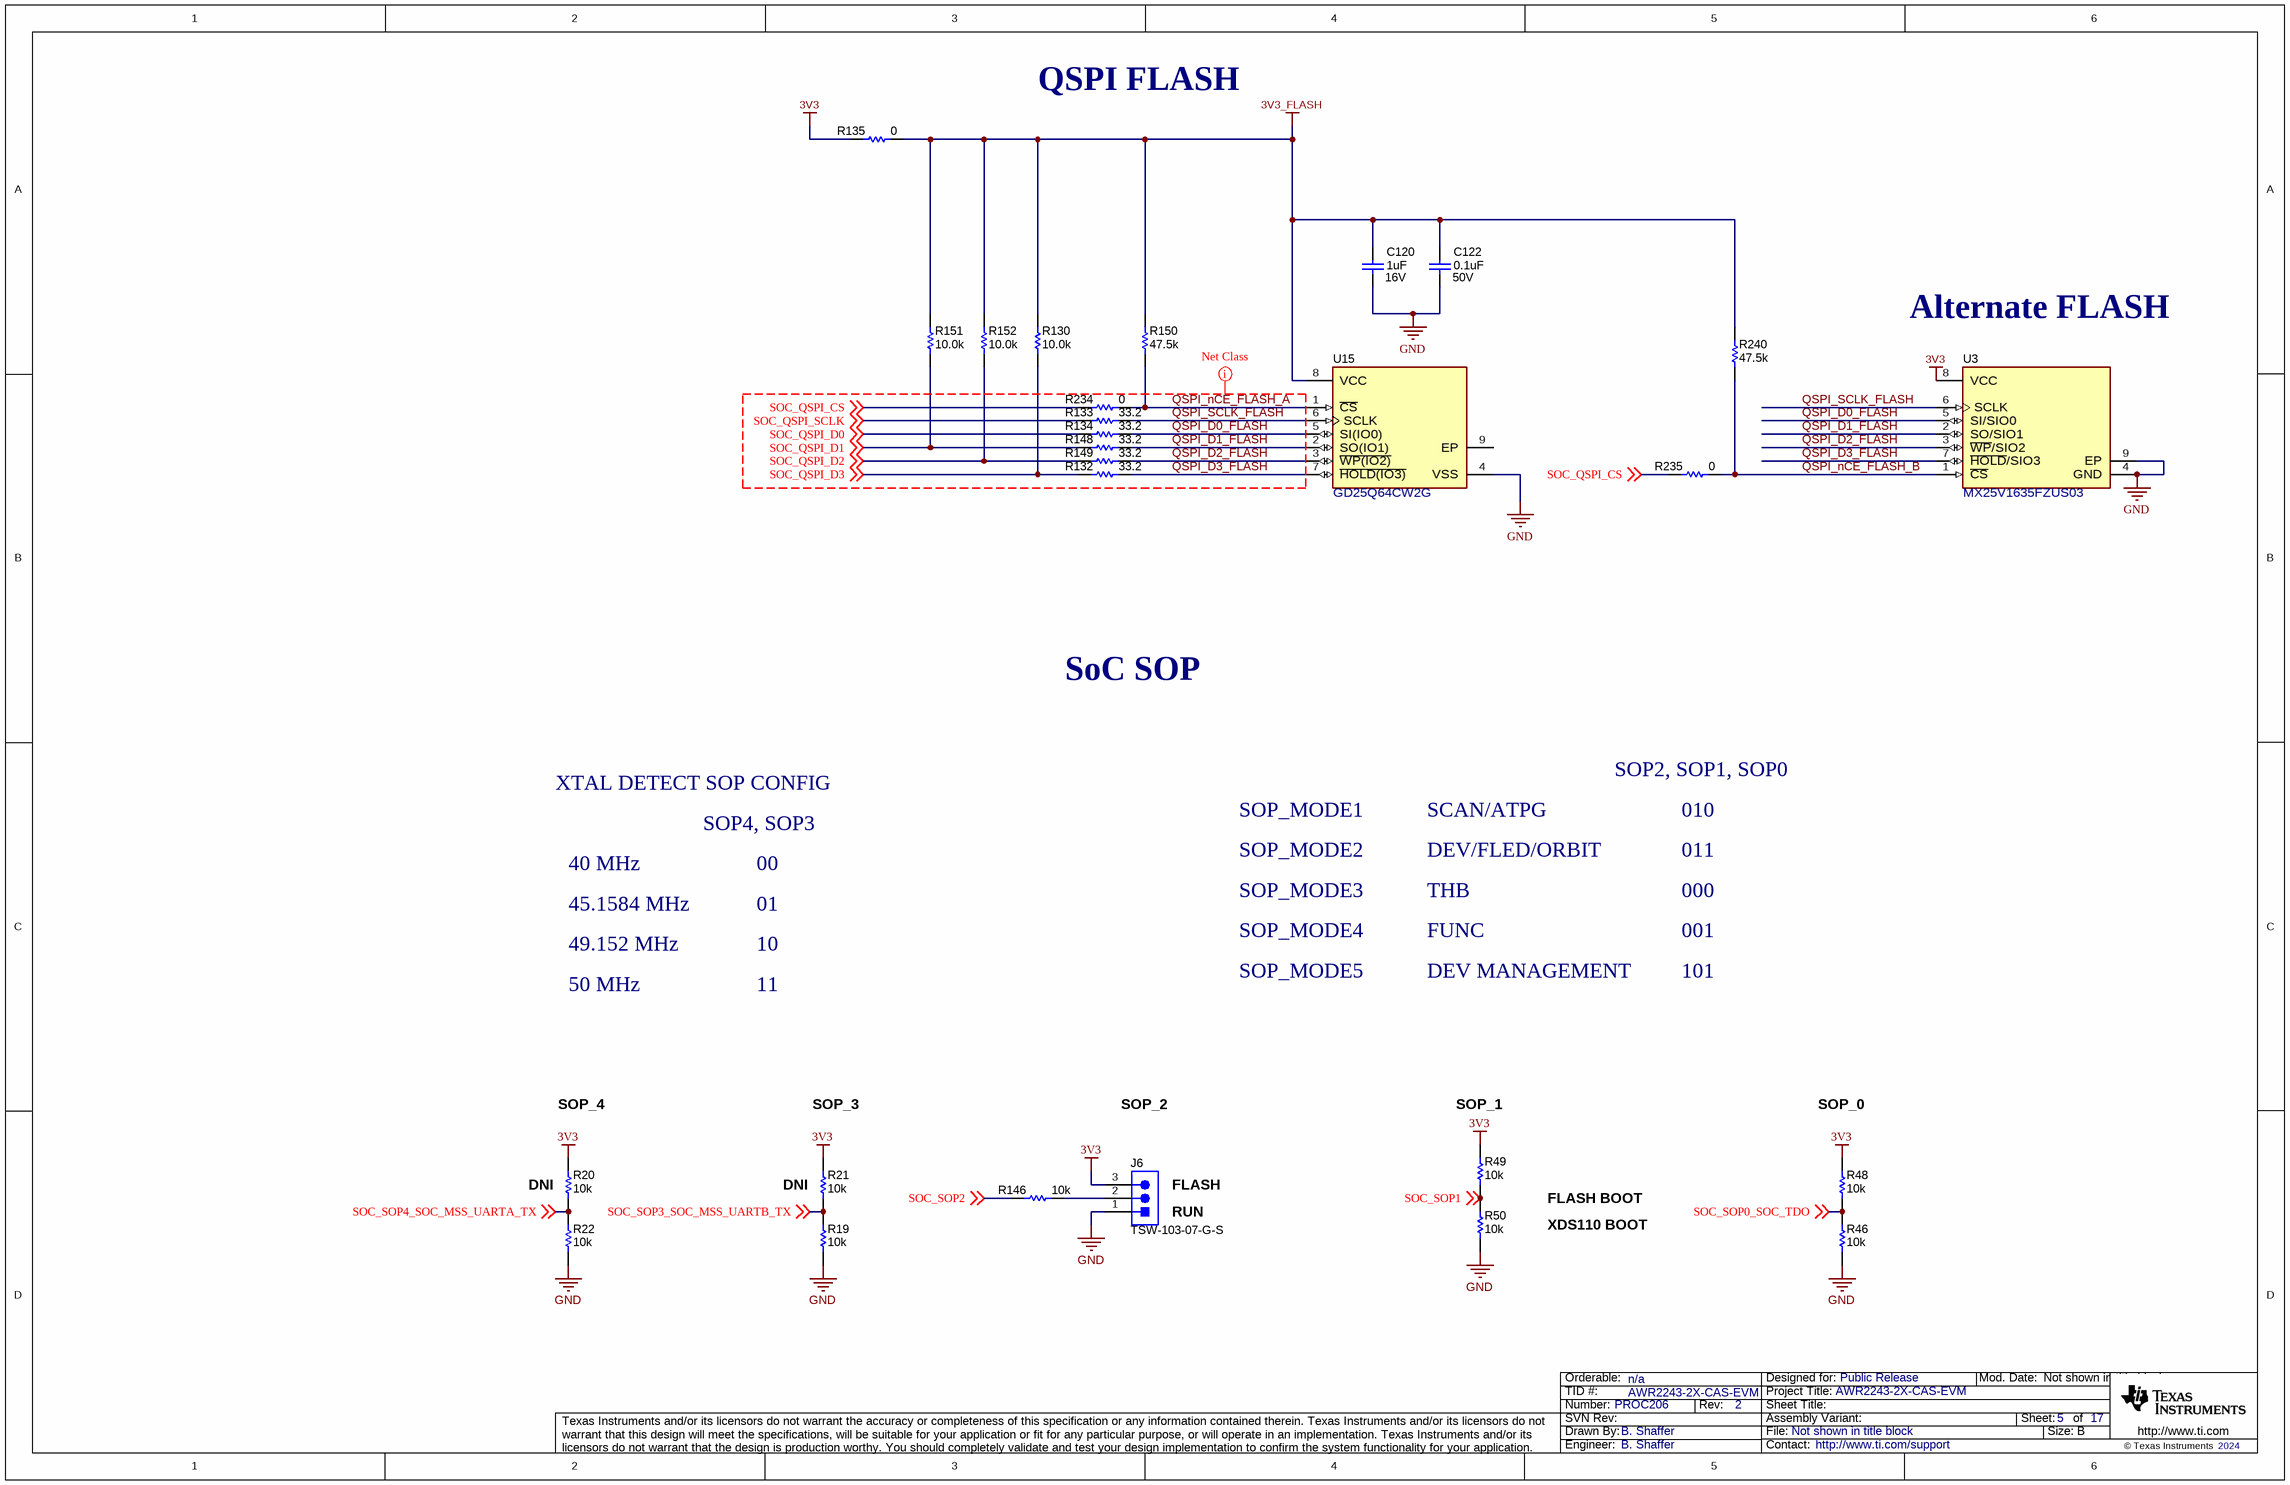
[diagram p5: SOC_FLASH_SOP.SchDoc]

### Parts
C120  VDC_V: 16V  ValueDisplayed: 1uF  [0603]  (hidden comment: GCM188R71C105KA64D)
C122  VDC_V: 50V  ValueDisplayed: 0.1uF  [0402L]  (hidden comment: CGA2B3X7R1H104K050BB)
J6  TSW-103-07-G-S  [TSW-103-07-X-S]
R19  ValueDisplayed: 10k  [0402]  (hidden comment: CRCW040210K0JNED)
R20  ValueDisplayed: 10k  [0402]  (hidden comment: CRCW040210K0JNED)
R21  ValueDisplayed: 10k  [0402]  (hidden comment: CRCW040210K0JNED)
R22  ValueDisplayed: 10k  [0402]  (hidden comment: CRCW040210K0JNED)
R46  ValueDisplayed: 10k  [0402]  (hidden comment: CRCW040210K0JNED)
R48  ValueDisplayed: 10k  [0402]  (hidden comment: CRCW040210K0JNED)
R49  ValueDisplayed: 10k  [0402]  (hidden comment: CRCW040210K0JNED)
R50  ValueDisplayed: 10k  [0402]  (hidden comment: CRCW040210K0JNED)
R130  ValueDisplayed: 10.0k  [0402L]  (hidden comment: CRCW040210K0FKED)
R132  ValueDisplayed: 33.2  [0201_Silk]  (hidden comment: CRCW020133R2FNED)
R133  ValueDisplayed: 33.2  [0201_Silk]  (hidden comment: CRCW020133R2FNED)
R134  ValueDisplayed: 33.2  [0201_Silk]  (hidden comment: CRCW020133R2FNED)
R135  ValueDisplayed: 0  [0402L]  (hidden comment: ERJ-2GE0R00X)
R146  ValueDisplayed: 10k  [0402]  (hidden comment: CRCW040210K0JNED)
R148  ValueDisplayed: 33.2  [0201_Silk]  (hidden comment: CRCW020133R2FNED)
R149  ValueDisplayed: 33.2  [0201_Silk]  (hidden comment: CRCW020133R2FNED)
R150  ValueDisplayed: 47.5k  [0402L]  (hidden comment: CRCW040247K5FKED)
R151  ValueDisplayed: 10.0k  [0402L]  (hidden comment: CRCW040210K0FKED)
R152  ValueDisplayed: 10.0k  [0402L]  (hidden comment: CRCW040210K0FKED)
R234  ValueDisplayed: 0  [0402L]  (hidden comment: ERJ-2GE0R00X)
R235  ValueDisplayed: 0  [0402L]  (hidden comment: ERJ-2GE0R00X)
R240  ValueDisplayed: 47.5k  [0402L]  (hidden comment: CRCW040247K5FKED)
U3  MX25V1635FZUS03  [FP-MX25V1635FZUS03_USON8-MFG]
U15  GD25Q64CW2G  [FP-GD25Q64CW2G_WSON8-IPC_C]

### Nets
3V3: J6.3 R20.2 R21.2 R48.2 R49.2 R135.2 U3.8(VCC)
3V3_FLASH: C120.2 C122.2 R130.2 R135.1 R150.2 R151.2 R152.2 R240.2 U15.8(VCC)
GND: C120.1 C122.1 J6.1 R19.1 R22.1 R46.1 R50.1 U3.4(GND) U3.9(EP) U15.4(VSS)
QSPI_D0_FLASH: R134.1 U3.5(SI/SIO0) U15.5(SI(IO0))
QSPI_D1_FLASH: R148.2 U3.2(SO/SIO1) U15.2(SO(IO1))
QSPI_D2_FLASH: R149.2 U3.3(~{WP}/SIO2) U15.3(~{WP(IO2)})
QSPI_D3_FLASH: R132.1 U3.7(~{HOLD}/SIO3) U15.7(~{HOLD(IO3)})
QSPI_nCE_FLASH_A: R150.1 R234.1 U15.1(~{CS})
QSPI_nCE_FLASH_B: R235.1 R240.1 U3.1(~{CS})
QSPI_SCLK_FLASH: R133.1 U3.6(SCLK) U15.6(SCLK)
SOC_QSPI_CS: R234.2 R235.2 ; off-sheet SOC_QSPI_CS
SOC_QSPI_D0: R134.2 ; off-sheet SOC_QSPI_D0
SOC_QSPI_D1: R148.1 R151.1 ; off-sheet SOC_QSPI_D1
SOC_QSPI_D2: R149.1 R152.1 ; off-sheet SOC_QSPI_D2
SOC_QSPI_D3: R130.1 R132.2 ; off-sheet SOC_QSPI_D3
SOC_QSPI_SCLK: R133.2 ; off-sheet SOC_QSPI_SCLK
SOC_SOP0_SOC_TDO: R46.2 R48.1 ; off-sheet SOC_SOP0_SOC_TDO
SOC_SOP1: R49.1 R50.2 ; off-sheet SOC_SOP1
SOC_SOP2: R146.2 ; off-sheet SOC_SOP2
SOC_SOP3_SOC_MSS_UARTB_TX: R19.2 R21.1 ; off-sheet SOC_SOP3_SOC_MSS_UARTB_TX
SOC_SOP4_SOC_MSS_UARTA_TX: R20.1 R22.2 ; off-sheet SOC_SOP4_SOC_MSS_UARTA_TX
NetJ6_2: J6.2 R146.1

Not connected (* = marked no-connect by the designer): U15 9(EP)

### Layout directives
net class QSPI: QSPI_D0_FLASH, QSPI_D1_FLASH, QSPI_D2_FLASH, QSPI_D3_FLASH, QSPI_nCE_FLASH_A, QSPI_SCLK_FLASH, SOC_QSPI_CS, SOC_QSPI_D0, SOC_QSPI_D1, SOC_QSPI_D2, SOC_QSPI_D3, SOC_QSPI_SCLK

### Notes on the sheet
- QSPI FLASH
- Alternate FLASH
- SoC SOP
- XTAL DETECT SOP CONFIG
- SOP4, SOP3
- SOP_MODE1
- SCAN/ATPG
- SOP2, SOP1, SOP0
- 010
- 40 MHz
- 00
- SOP_MODE2
- SOP_MODE3
- DEV/FLED/ORBIT
- THB
- 011
- 000
- 45.1584 MHz
- 49.152 MHz
- 01
- 10
- SOP_MODE4
- FUNC
- 001
- 50 MHz
- 11
- SOP_MODE5
- DEV MANAGEMENT
- 101
- SOP_4
- SOP_3
- SOP_2
- (near R49) SOP_1
- SOP_0
- (near R20) DNI
- (near R21) DNI
- (near J6) FLASH
- (near J6) RUN
- FLASH BOOT
- XDS110 BOOT

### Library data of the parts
C120 = CMP-0007136-5: CAP, CERM, 1 uF, 16 V, +/- 10%, X7R, AEC-Q200 Grade 1, 0603; Manufacturer: MuRata; TaMin_C: -55°C; Polarized: N; SizeAreaWB_mm2: 4.68; Value1: Unknown; U/M: EA; Value: 1uF; TaMax_C: 125°C; SizeZ_mm: 1; SizeX_mm: 1.6; SizeY_mm: 0.8; SizeArea_mm2: 1.28; CompType: Capacitor; AEC Qualified: Y; Cap_F: 1µF; AEC Category: Q200
C122 = CMP-0006325-2: CAP, CERM, 0.1 uF, 50 V, +/- 10%, X7R, AEC-Q200 Grade 1, 0402; Manufacturer: TDK; TaMin_C: -55°C; ESR_ohm: 0.039064; Polarized: N; SizeAreaWB_mm2: 3; Value1: 0.039064 ohm; U/M: EA; Value: 0.1uF; TaMax_C: 125°C; SizeZ_mm: 0.6; SizeX_mm: 1; SizeY_mm: 0.5; Cap_Case: 0402; CompType: Capacitor; AEC Qualified: Y; Cap_F: 100nF; IRMS_A: 8.14669dA; AEC Category: Q200
J6 = CMP-0075407-1: Header, 100mil, 3x1, Gold, TH; Manufacturer: Samtec; Pitch_mm: 2.54; Cert_VDE: N; Gender: Male; Cert_CSA: Y; Voltage_V: 550V; Green_REACh: Passed; Current_A: 6.3A; CT: False; Green_Lifecycle: Active; Row_Count: 1; CNHeader: True
R19-R22 R46 R48-R50 R146 = CMP-0026825-4: RES, 10 k, 5%, 0.063 W, 0402; Manufacturer: Vishay-Dale; Power_W: 63mW; TempCo: 200 ppm/C; Value_Code: 10k0; U/M: EA; Value: 10k; EIA_Code: E24; SizeX_mm: 1; SizeY_mm: 0.5; SizeZ_mm: 0.6; Value2: 0.063W; VDC_V: 50V; AEC Category: Q200
R130 R151 R152 = CMP-0025958-3: RES, 10.0 k, 1%, 0.063 W, AEC-Q200 Grade 0, 0402; Manufacturer: Vishay-Dale; Power_W: 63mW; TempCo: 100 ppm/C; Value_Code: 10k0; Value: 10.0k; EIA_Code: E96; Res_ohm: 10k; SizeX_mm: 1; SizeY_mm: 0.5; SizeZ_mm: 0.6; Value2: 0.063W; AEC Qualified: Y; VDC_V: 50V; AEC Category: Q200; AEC Grade: 0
R132-R134 R148 R149 = CMP-0027275-3: RES, 33.2, 1%, 0.05 W, 0201; Manufacturer: Vishay-Dale; Power_W: 50mW; TempCo: 200 ppm/C; Value_Code: 33R2; Value: 33.2; EIA_Code: E96; SizeX_mm: 0.6; SizeY_mm: 0.3; SizeZ_mm: 0.26; Value2: 0.05W; SizeArea_mm2: 0.18; AEC Qualified: N; AEC Category: Q200
R135 R234 R235 = CMP-0026992-3: RES, 0, 5%, 0.1 W, AEC-Q200 Grade 0, 0402; Manufacturer: Panasonic; Power_W: 100mW; TempCo: 600 ppm/C; Value_Code: 0000; Value: 0; EIA_Code: E24; SizeX_mm: 1; SizeY_mm: 0.5; SizeZ_mm: 0.6; Value2: 0.1W; CompType: Resistor; AEC Qualified: Y; VDC_V: 50V; AEC Category: Q200; SizeAreaWB_mm2: 3
R150 R240 = CMP-0026395-2: RES, 47.5 k, 1%, 0.063 W, AEC-Q200 Grade 0, 0402; Manufacturer: Vishay-Dale; Power_W: 63mW; TempCo: 100 ppm/C; Value_Code: 47k5; Value: 47.5k; EIA_Code: E96; SizeX_mm: 1; SizeY_mm: 0.5; SizeZ_mm: 0.6; Value2: 0.063W; AEC Qualified: Y; VDC_V: 50V; AEC Category: Q200; AEC Grade: 0
U3 = CMP-0089721-1: FLASH - NOR Memory IC 16Mb (2M x 8) SPI 80MHz 8-USON (2x3); Manufacturer: Macronix; Access Time: 8ns; Nominal Supply Current: 3.5-6.5mA; TaMin_C: -40°C; Min Supply Voltage: 2.3V; Memory Type: FLASH,NOR; AEC Grade: Grade 3; TaMax_C: +85°C; Max Supply Voltage: 3.6V; AEC Qualified: Yes; SizeZ_mm: 0.6mm; Memory Size: 16Mbits; Standoff Height: 0mm
U15 = CMP-0091167-2: 3.3V Uniform Sector Dual and Quad Serial Flash; Manufacturer: GigaDevice; AEC Qualified: Yes; Max Supply Voltage: 3.6V; Frequency_Fixed: 120MHz; Interface: SPI; TaMax_C: +85°C; AEC Grade: Grade 2; Standoff Height: 0mm; Min Supply Voltage: 2.7V; SizeZ_mm: 0.8mm; TaMin_C: -40°C

## Sheet FE1_PWR.SchDoc
size 431 x 279 mm; Date: Not shown in title block; ApprovedBy: Not shown in title block; CheckedBy: Not shown in title block; Author: Not shown in title block; CompanyName: Not shown in title block; DrawnBy: B. Shaffer; Engineer: Not shown in title block; Organization: Not shown in title block; Address1: Not shown in title block; Address2: Not shown in title block; Address3: Not shown in title block; Address4: Not shown in title block; DocumentNumber: 6; Revision: Use project parameter SCH_Rev; SheetNumber: 6; SheetTotal: 17; PageSetup: Record=PageOptions¦CenterHorizontal=True¦CenterVertical=True¦PrintScale=1.00¦XCorrection=1.00¦YCorrection=1.00¦PrintKind=0¦BorderSize=5000000¦LeftOffset=0¦BottomOffset=0¦Orientation=2¦PaperLength=1000¦PaperWidth=1000¦Scale=100¦PaperSource=15¦PrintQuality=600¦MediaType=1¦DitherType=10¦PaperKind=Letter¦PrintScaleMode=1
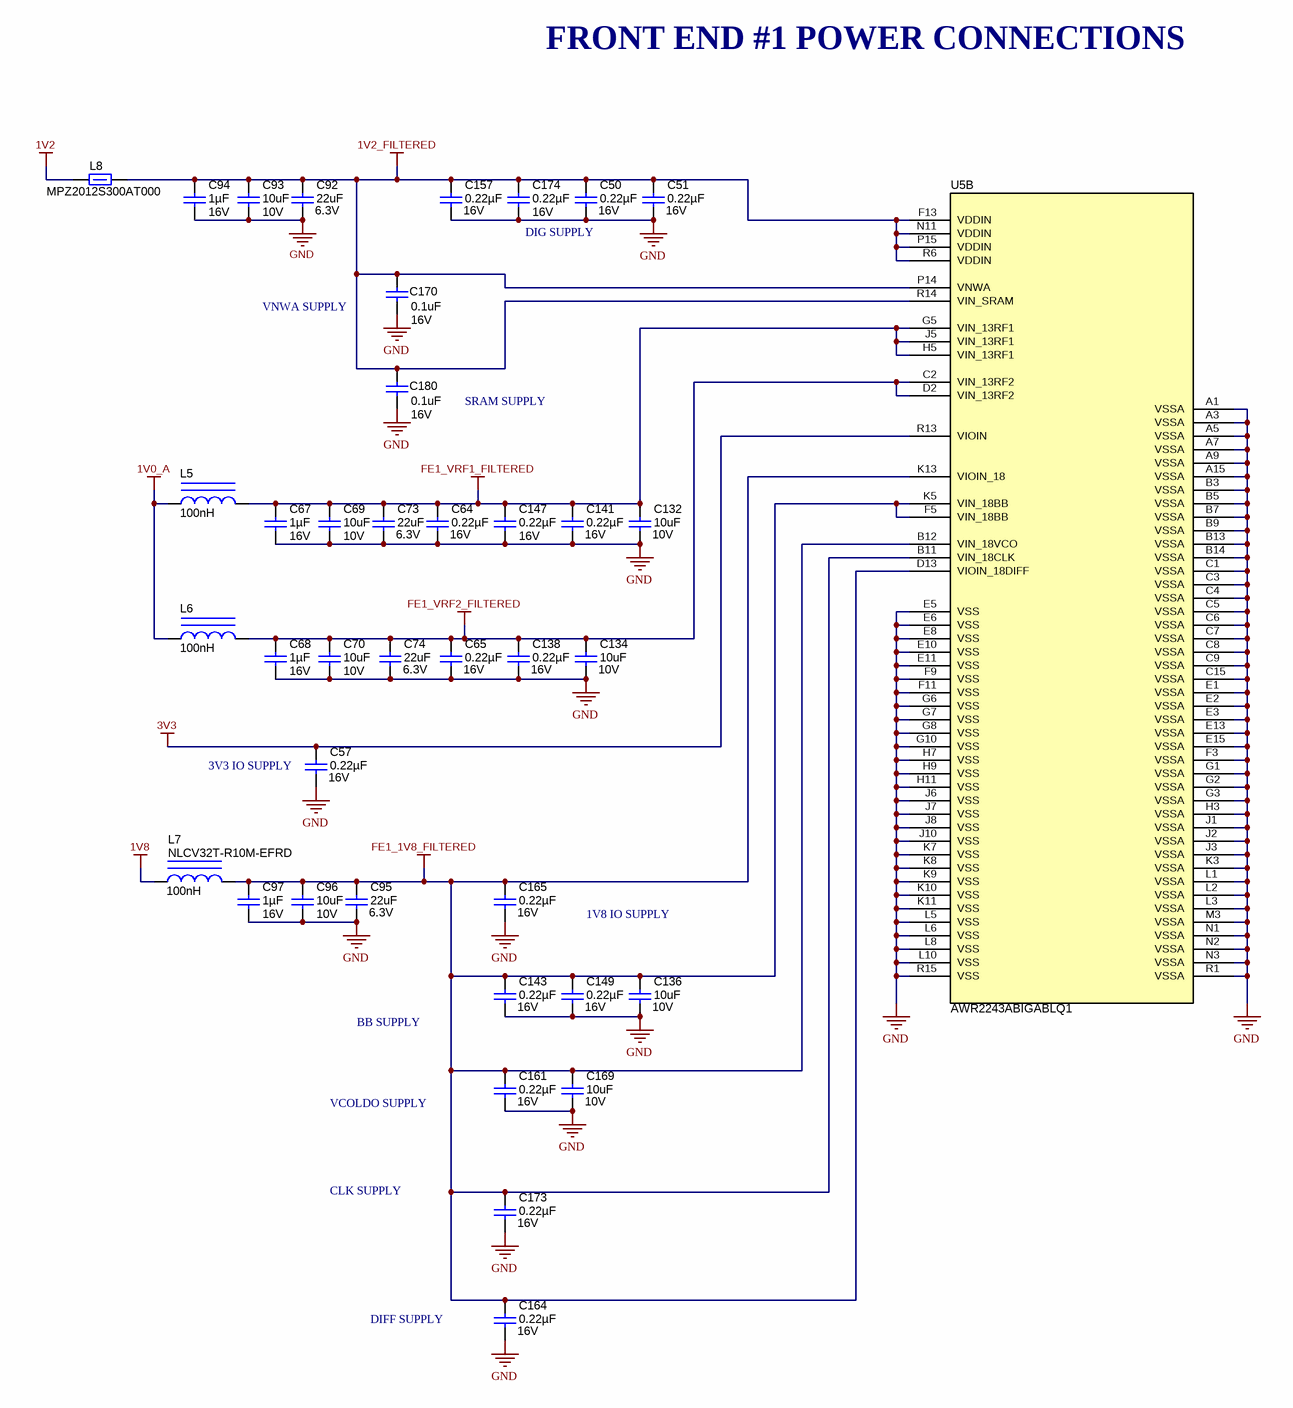
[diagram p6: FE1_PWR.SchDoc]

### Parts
(Parts that share a designator on the sheet are numbered #1, #2 ... from top to bottom, then left to right.)
C50  VDC_V: 16V  ValueDisplayed: 0.22µF  [0402L]  (hidden comment: GCM155R71C224KE02D)
C51  VDC_V: 16V  ValueDisplayed: 0.22µF  [0402L]  (hidden comment: GCM155R71C224KE02D)
C57  VDC_V: 16V  ValueDisplayed: 0.22µF  [0402L]  (hidden comment: GCM155R71C224KE02D)
C64  VDC_V: 16V  ValueDisplayed: 0.22µF  [0402L]  (hidden comment: GCM155R71C224KE02D)
C65  VDC_V: 16V  ValueDisplayed: 0.22µF  [0402L]  (hidden comment: GCM155R71C224KE02D)
C67  VDC_V: 16V  ValueDisplayed: 1µF  [0603S]  (hidden comment: GCM188R71C105KA64J)
C68  VDC_V: 16V  ValueDisplayed: 1µF  [0603S]  (hidden comment: GCM188R71C105KA64J)
C69  VDC_V: 10V  ValueDisplayed: 10uF  [0805L]  (hidden comment: GCM21BR71A106KE22L)
C70  VDC_V: 10V  ValueDisplayed: 10uF  [0805L]  (hidden comment: GCM21BR71A106KE22L)
C73  VDC_V: 6.3V  ValueDisplayed: 22uF  [0805]  (hidden comment: GCM21BD70J226ME36L)
C74  VDC_V: 6.3V  ValueDisplayed: 22uF  [0805]  (hidden comment: GCM21BD70J226ME36L)
C92  VDC_V: 6.3V  ValueDisplayed: 22uF  [0805]  (hidden comment: GCM21BD70J226ME36L)
C93  VDC_V: 10V  ValueDisplayed: 10uF  [0805L]  (hidden comment: GCM21BR71A106KE22L)
C94  VDC_V: 16V  ValueDisplayed: 1µF  [0603S]  (hidden comment: GCM188R71C105KA64J)
C95  VDC_V: 6.3V  ValueDisplayed: 22uF  [0805]  (hidden comment: GCM21BD70J226ME36L)
C96  VDC_V: 10V  ValueDisplayed: 10uF  [0805L]  (hidden comment: GCM21BR71A106KE22L)
C97  VDC_V: 16V  ValueDisplayed: 1µF  [0603S]  (hidden comment: GCM188R71C105KA64J)
C132  VDC_V: 10V  ValueDisplayed: 10uF  [0805_HV1]  (hidden comment: GCM21BR71A106KE22L)
C134  VDC_V: 10V  ValueDisplayed: 10uF  [0805]  (hidden comment: GCM21BR71A106KE22L)
C136  VDC_V: 10V  ValueDisplayed: 10uF  [0805_HV]  (hidden comment: GCM21BR71A106KE22L)
C138  VDC_V: 16V  ValueDisplayed: 0.22µF  [0402]  (hidden comment: GCM155R71C224KE02D)
C141  VDC_V: 16V  ValueDisplayed: 0.22µF  [0402L]  (hidden comment: GCM155R71C224KE02D)
C143  VDC_V: 16V  ValueDisplayed: 0.22µF  [0402L]  (hidden comment: GCM155R71C224KE02D)
C147  VDC_V: 16V  ValueDisplayed: 0.22µF  [0402L]  (hidden comment: GCM155R71C224KE02D)
C149  VDC_V: 16V  ValueDisplayed: 0.22µF  [0402]  (hidden comment: GCM155R71C224KE02D)
C157  VDC_V: 16V  ValueDisplayed: 0.22µF  [0402L]  (hidden comment: GCM155R71C224KE02D)
C161  VDC_V: 16V  ValueDisplayed: 0.22µF  [0402]  (hidden comment: GCM155R71C224KE02D)
C164  VDC_V: 16V  ValueDisplayed: 0.22µF  [0402]  (hidden comment: GCM155R71C224KE02D)
C165  VDC_V: 16V  ValueDisplayed: 0.22µF  [0402]  (hidden comment: GCM155R71C224KE02D)
C169  VDC_V: 10V  ValueDisplayed: 10uF  [0805_HV]  (hidden comment: GCM21BR71A106KE22L)
C170  VDC_V: 16V  ValueDisplayed: 0.1uF  [0402]  (hidden comment: GCM155R71C104KA55D)
C173  VDC_V: 16V  ValueDisplayed: 0.22µF  [0402L]  (hidden comment: GCM155R71C224KE02D)
C174  VDC_V: 16V  ValueDisplayed: 0.22µF  [0402L]  (hidden comment: GCM155R71C224KE02D)
C180  VDC_V: 16V  ValueDisplayed: 0.1uF  [0402L]  (hidden comment: GCM155R71C104KA55D)
L5  ValueDisplayed: 100nH  [NLCV32]  (hidden comment: NLCV32T-R10M-EFRD)
L6  ValueDisplayed: 100nH  [NLCV32]  (hidden comment: NLCV32T-R10M-EFRD)
L7  ValueDisplayed: 100nH  [NLCV32]  (hidden comment: NLCV32T-R10M-EFRD)
L8  MPZ2012S300AT000  [MPZ2012]
U5#1  AWR2243ABIGABLQ1  [ABL0161A]  (part B of 2)

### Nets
1V0_A: L5.1 L6.1
1V2: L8.1
1V2_FILTERED: C50.1 C51.1 C92.1 C93.1 C94.1 C157.1 C170.1 C174.1 C180.1 L8.2 U5#1.F13(VDDIN) U5#1.N11(VDDIN) U5#1.P14(VNWA) U5#1.P15(VDDIN) U5#1.R6(VDDIN) U5#1.R14(VIN_SRAM)
1V8: L7.1
3V3: C57.1 U5#1.R13(VIOIN)
FE1_1V8_FILTERED: C95.1 C96.1 C97.1 C136.1 C143.1 C149.1 C161.1 C164.1 C165.1 C169.1 C173.1 L7.2 U5#1.B11(VIN_18CLK) U5#1.B12(VIN_18VCO) U5#1.D13(VIOIN_18DIFF) U5#1.F5(VIN_18BB) U5#1.K5(VIN_18BB) U5#1.K13(VIOIN_18)
FE1_VRF1_FILTERED: C64.1 C67.1 C69.1 C73.1 C132.1 C141.1 C147.1 L5.2 U5#1.G5(VIN_13RF1) U5#1.H5(VIN_13RF1) U5#1.J5(VIN_13RF1)
FE1_VRF2_FILTERED: C65.1 C68.1 C70.1 C74.1 C134.1 C138.1 L6.2 U5#1.C2(VIN_13RF2) U5#1.D2(VIN_13RF2)
GND: C50.2 C51.2 C57.2 C64.2 C65.2 C67.2 C68.2 C69.2 C70.2 C73.2 C74.2 C92.2 C93.2 C94.2 C95.2 C96.2 C97.2 C132.2 C134.2 C136.2 C138.2 C141.2 C143.2 C147.2 C149.2 C157.2 C161.2 C164.2 C165.2 C169.2 C170.2 C173.2 C174.2 C180.2 U5#1.A1(VSSA) U5#1.A3(VSSA) U5#1.A5(VSSA) U5#1.A7(VSSA) U5#1.A9(VSSA) U5#1.A15(VSSA) U5#1.B3(VSSA) U5#1.B5(VSSA) U5#1.B7(VSSA) U5#1.B9(VSSA) U5#1.B13(VSSA) U5#1.B14(VSSA) U5#1.C1(VSSA) U5#1.C3(VSSA) U5#1.C4(VSSA) U5#1.C5(VSSA) U5#1.C6(VSSA) U5#1.C7(VSSA) U5#1.C8(VSSA) U5#1.C9(VSSA) U5#1.C15(VSSA) U5#1.E1(VSSA) U5#1.E2(VSSA) U5#1.E3(VSSA) U5#1.E5(VSS) U5#1.E6(VSS) U5#1.E8(VSS) U5#1.E10(VSS) U5#1.E11(VSS) U5#1.E13(VSSA) U5#1.E15(VSSA) U5#1.F3(VSSA) U5#1.F9(VSS) U5#1.F11(VSS) U5#1.G1(VSSA) U5#1.G2(VSSA) U5#1.G3(VSSA) U5#1.G6(VSS) U5#1.G7(VSS) U5#1.G8(VSS) U5#1.G10(VSS) U5#1.H3(VSSA) U5#1.H7(VSS) U5#1.H9(VSS) U5#1.H11(VSS) U5#1.J1(VSSA) U5#1.J2(VSSA) U5#1.J3(VSSA) U5#1.J6(VSS) U5#1.J7(VSS) U5#1.J8(VSS) U5#1.J10(VSS) U5#1.K3(VSSA) U5#1.K7(VSS) U5#1.K8(VSS) U5#1.K9(VSS) U5#1.K10(VSS) U5#1.K11(VSS) U5#1.L1(VSSA) U5#1.L2(VSSA) U5#1.L3(VSSA) U5#1.L5(VSS) U5#1.L6(VSS) U5#1.L8(VSS) U5#1.L10(VSS) U5#1.M3(VSSA) U5#1.N1(VSSA) U5#1.N2(VSSA) U5#1.N3(VSSA) U5#1.R1(VSSA) U5#1.R15(VSS)

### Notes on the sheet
- FRONT END #1 POWER CONNECTIONS
- DIG SUPPLY
- VNWA SUPPLY
- SRAM SUPPLY
- (near C57) 3V3 IO SUPPLY
- 1V8 IO SUPPLY
- BB SUPPLY
- VCOLDO SUPPLY
- CLK SUPPLY
- DIFF SUPPLY

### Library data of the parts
C50 C51 C57 C64 C65 C141 C143 C147 C157 C173 C174 = CMP-0078265-1: CAP, CERM, 0.22 µF, 16 V,+/- 10%, X7R, AEC-Q200 Grade 1, 0402; Manufacturer: MuRata; TaMin_C: -55°C; Polarized: N; SizeAreaWB_mm2: 3; U/M: EA; Value: 0.22uF; TaMax_C: 125°C; SizeZ_mm: 0.6; SizeX_mm: 1; SizeY_mm: 0.5; Cap_Case: 0402; CompType: Capacitor; AEC Qualified: Y; Cap_F: 220nF; AEC Category: Q200
C67 C68 C94 C97 = CMP-0079154-1: as C25 on sheet SOC_IO
C69 C70 C93 C96 = CMP-0008017-2: CAP, CERM, 10 uF, 10 V, +/- 10%, X7R, 0805; Manufacturer: MuRata; TaMin_C: -55°C; Polarized: N; SizeAreaWB_mm2: 6.75; Value1: Unknown; U/M: EA; Value: 10uF; TaMax_C: 125°C; SizeZ_mm: 1.45; SizeX_mm: 2; SizeY_mm: 1.25; Cap_Case: 0805; SizeArea_mm2: 2.5; Cap_F: 10µF; AEC Category: Q200
C73 C74 C92 C95 = CMP-0008015-1: CAP, CERM, 22 uF, 6.3 V, +/- 20%, X7T, AEC-Q200 Grade 1, 0805; Manufacturer: MuRata; TaMin_C: -55°C; Polarized: N; SizeAreaWB_mm2: 6.75; Value1: Unknown; U/M: EA; Value: 22uF; TaMax_C: 125°C; SizeZ_mm: 1.45; SizeX_mm: 2; SizeY_mm: 1.25; SizeArea_mm2: 2.5; CompType: Capacitor; AEC Qualified: Y; Cap_F: 22µF; AEC Grade: 1; AEC Category: Q200
C132 C136 C169 = CMP-0008017-2: CAP, CERM, 10 uF, 10 V, +/- 10%, X7R, 0805; Manufacturer: MuRata; TaMin_C: -55°C; Polarized: N; SizeAreaWB_mm2: 6.75; Value1: Unknown; U/M: EA; Value: 10uF; TaMax_C: 125°C; SizeZ_mm: 1.45; SizeX_mm: 2; SizeY_mm: 1.25; Cap_Case: 0805; SizeArea_mm2: 2.5; CompType: Capacitor; Cap_F: 10µF; AEC Category: Q200
C134 = CMP-0008017-2: CAP, CERM, 10 uF, 10 V, +/- 10%, X7R, 0805; Manufacturer: MuRata; TaMin_C: -55°C; Polarized: N; SizeAreaWB_mm2: 6.75; Value1: Unknown; U/M: EA; Value: 10uF; TaMax_C: 125°C; SizeZ_mm: 1.45; SizeX_mm: 2; SizeY_mm: 1.25; SizeArea_mm2: 2.5; CompType: Capacitor; Cap_F: 10µF; AEC Category: Q200
C138 C149 C161 C164 C165 = CMP-0078265-1: CAP, CERM, 0.22 µF, 16 V,+/- 10%, X7R, AEC-Q200 Grade 1, 0402; Manufacturer: MuRata; TaMin_C: -55°C; Polarized: N; SizeAreaWB_mm2: 3; U/M: EA; Value: 0.22uF; TaMax_C: 125°C; SizeZ_mm: 0.6; SizeX_mm: 1; SizeY_mm: 0.5; CompType: Capacitor; AEC Qualified: Y; Cap_F: 220nF; AEC Category: Q200
C170 = CMP-0006351-2: CAP, CERM, 0.1 uF, 16 V, +/- 10%, X7R, 0402; Manufacturer: MuRata; TaMin_C: -55°C; Polarized: N; SizeAreaWB_mm2: 3; Value1: Unknown; U/M: EA; Value: 0.1uF; TaMax_C: 125°C; SizeZ_mm: 0.6; SizeX_mm: 1; SizeY_mm: 0.5; CompType: Capacitor; Cap_F: 100nF; AEC Category: Q200
C180 = CMP-0006351-2: CAP, CERM, 0.1 uF, 16 V, +/- 10%, X7R, 0402; Manufacturer: MuRata; TaMin_C: -55°C; Polarized: N; SizeAreaWB_mm2: 3; Value1: Unknown; U/M: EA; Value: 0.1uF; TaMax_C: 125°C; SizeZ_mm: 0.6; SizeX_mm: 1; SizeY_mm: 0.5; Cap_Case: 0402; CompType: Capacitor; Cap_F: 100nF; AEC Category: Q200
L5-L7 = CMP-0083745-1: Inductor, Wirewound, Ferrite, 100 nH, 2.85 A, 0.024 ohm, AEC-Q200 Grade 1, SMD; Manufacturer: TDK; Isat: 2.85A @ 10% inductance drop; Irms: 2.85A @ 40C rise; SizeAreaWB_mm2: 13.44; DCR_ohm: 0.024; Value: 100nH; Imax_A: 2.85A; SizeZ_mm: 2.5; SizeX_mm: 3.2; SizeY_mm: 2.2; SizeArea_mm2: 7.04; AEC Qualified: Y; AEC Grade: 1; AEC Category: Q200
L8 = CMP-0003428-2: Ferrite Bead, 30 ohm @ 100 MHz, 6 A, 0805; Manufacturer: TDK; ZTyp@100MHz_Ohm: 30; SizeAreaWB_mm2: 6.75; DCR_ohm: 0.01; Value1: 0.01 ohm; Value: 30 ohm; Imax_A: 6A; SizeZ_mm: 1.45; SizeX_mm: 2; SizeY_mm: 1.25; SizeArea_mm2: 2.5
U5#1 = CMP-0082537-1: Single Chip 77 and 79 GHz FMCW Transceiver, ABL0161A (FCBGA-161); Alternate Manufacturer: Texas Instruments; SizeAreaWB_mm2: 153.76; Rating: Automotive; SizeZ_mm: 1.17; SizeX_mm: 10.4; SizeArea_mm2: 108.16; CompType: IC; AEC Qualified: Y; AEC Category: Q200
